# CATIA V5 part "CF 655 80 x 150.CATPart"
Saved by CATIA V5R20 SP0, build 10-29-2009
Part number: CF 655 80 x 150
Definition: NONE
Nomenclature: CF 655 80 x 150
Source: Unknown
Description: CF 655 80 x 150
Bounding box of the stored display mesh (mm): x -102 to 48, y -55.5 to 55.5, z -55.5 to 55.5
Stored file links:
  C:\Users\Utente\Desktop\IO LAVORO\3D X SITO CF\X SITO\CF 655\CF 655 80 x 150.CATPart
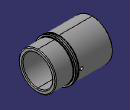
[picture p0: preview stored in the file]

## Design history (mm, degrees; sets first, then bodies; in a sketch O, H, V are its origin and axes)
Body1 "CF 655 80 x 150" (main body)
  Solid1: solid without history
